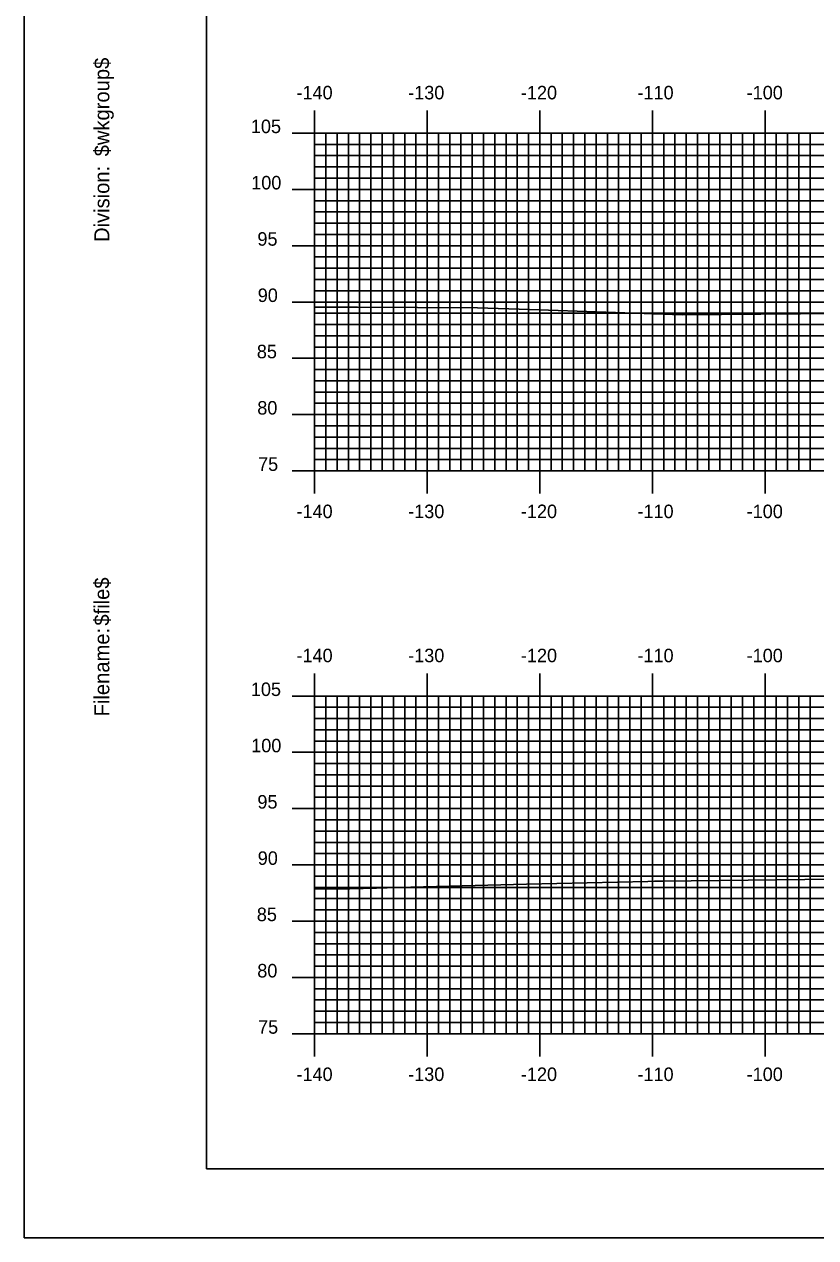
# Model space of a CAD drawing. Extents: x 854510 to 854853, y 364366 to 364586.
# Drawn here: x 854510 to 854580.2, y 364365.7 to 364473.5 of the extents above; entities that cross this region are included whole.
import ezdxf

# ---------------------------------------------------------------- set-up
doc = ezdxf.new("R2010")
doc.units = 0
for name, color, linetype in [('BORDER', 7, 'Continuous'), ('H_V ANNOTATION', 7, 'Continuous'), ('MAJOR', 7, 'Continuous'), ('MINOR', 7, 'Continuous'), ('PLOT BOUNDARY', 7, 'Continuous'), ('S_Roadway_Centerline', 7, 'Continuous')]:
    doc.layers.add(name, color=color, linetype=linetype)

msp = doc.modelspace()

# ---------------------------------------------------------------- linework, layer by layer
at = {"layer": 'BORDER'}
msp.add_lwpolyline([(854526.14, 364371.79), (854846.14, 364371.79), (854846.14, 364581.79), (854526.14, 364581.79)], close=True, dxfattribs=at)
at = {"layer": 'MAJOR'}
for p, q in [((854535.74, 364465.79), (854535.74, 364463.79)), ((854545.74, 364465.79), (854545.74, 364463.79)), ((854555.74, 364465.79), (854555.74, 364463.79)), ((854565.74, 364465.79), (854565.74, 364463.79)), ((854575.74, 364465.79), (854575.74, 364463.79)), ((854533.74, 364463.79), (854535.74, 364463.79)), ((854535.74, 364463.79), (854815.74, 364463.79)), ((854535.74, 364433.79), (854535.74, 364463.79)), ((854535.74, 364433.79), (854535.74, 364463.79)), ((854535.74, 364463.79), (854815.74, 364463.79)), ((854545.74, 364433.79), (854545.74, 364463.79)), ((854555.74, 364433.79), (854555.74, 364463.79)), ((854565.74, 364433.79), (854565.74, 364463.79)), ((854575.74, 364433.79), (854575.74, 364463.79)), ((854533.74, 364458.79), (854535.74, 364458.79)), ((854535.74, 364458.79), (854815.74, 364458.79)), ((854533.74, 364453.79), (854535.74, 364453.79)), ((854535.74, 364453.79), (854815.74, 364453.79)), ((854533.74, 364448.79), (854535.74, 364448.79)), ((854535.74, 364448.79), (854815.74, 364448.79)), ((854533.74, 364443.79), (854535.74, 364443.79)), ((854535.74, 364443.79), (854815.74, 364443.79)), ((854533.74, 364438.79), (854535.74, 364438.79)), ((854535.74, 364438.79), (854815.74, 364438.79)), ((854533.74, 364433.79), (854535.74, 364433.79)), ((854535.74, 364433.79), (854815.74, 364433.79)), ((854535.74, 364433.79), (854815.74, 364433.79)), ((854535.74, 364431.78), (854535.74, 364433.79)), ((854545.74, 364431.78), (854545.74, 364433.79)), ((854555.74, 364431.78), (854555.74, 364433.79)), ((854565.74, 364431.78), (854565.74, 364433.79)), ((854575.74, 364431.78), (854575.74, 364433.79)), ((854535.74, 364415.79), (854535.74, 364413.79)), ((854545.74, 364415.79), (854545.74, 364413.79)), ((854555.74, 364415.79), (854555.74, 364413.79)), ((854565.74, 364415.79), (854565.74, 364413.79)), ((854575.74, 364415.79), (854575.74, 364413.79)), ((854533.74, 364413.79), (854535.74, 364413.79)), ((854535.74, 364413.79), (854815.74, 364413.79)), ((854535.74, 364383.79), (854535.74, 364413.79)), ((854535.74, 364383.79), (854535.74, 364413.79)), ((854535.74, 364413.79), (854815.74, 364413.79)), ((854545.74, 364383.79), (854545.74, 364413.79)), ((854555.74, 364383.79), (854555.74, 364413.79)), ((854565.74, 364383.79), (854565.74, 364413.79)), ((854575.74, 364383.79), (854575.74, 364413.79)), ((854533.74, 364408.79), (854535.74, 364408.79)), ((854535.74, 364408.79), (854815.74, 364408.79)), ((854533.74, 364403.79), (854535.74, 364403.79)), ((854535.74, 364403.79), (854815.74, 364403.79)), ((854533.74, 364398.79), (854535.74, 364398.79)), ((854535.74, 364398.79), (854815.74, 364398.79)), ((854533.74, 364393.79), (854535.74, 364393.79)), ((854535.74, 364393.79), (854815.74, 364393.79)), ((854533.74, 364388.79), (854535.74, 364388.79)), ((854535.74, 364388.79), (854815.74, 364388.79)), ((854533.74, 364383.79), (854535.74, 364383.79)), ((854535.74, 364383.79), (854815.74, 364383.79)), ((854535.74, 364383.79), (854815.74, 364383.79)), ((854535.74, 364381.78), (854535.74, 364383.79)), ((854545.74, 364381.78), (854545.74, 364383.79)), ((854555.74, 364381.78), (854555.74, 364383.79)), ((854565.74, 364381.78), (854565.74, 364383.79)), ((854575.74, 364381.78), (854575.74, 364383.79))]:
    msp.add_line(p, q, dxfattribs=at)
at = {"layer": 'MINOR'}
for p, q in [((854536.74, 364433.79), (854536.74, 364463.79)), ((854537.74, 364433.79), (854537.74, 364463.79)), ((854538.74, 364433.79), (854538.74, 364463.79)), ((854539.74, 364433.79), (854539.74, 364463.79)), ((854540.74, 364433.79), (854540.74, 364463.79)), ((854541.74, 364433.79), (854541.74, 364463.79)), ((854542.74, 364433.79), (854542.74, 364463.79)), ((854543.74, 364433.79), (854543.74, 364463.79)), ((854544.74, 364433.79), (854544.74, 364463.79)), ((854546.74, 364433.79), (854546.74, 364463.79)), ((854547.74, 364433.79), (854547.74, 364463.79)), ((854548.74, 364433.79), (854548.74, 364463.79)), ((854549.74, 364433.79), (854549.74, 364463.79)), ((854550.74, 364433.79), (854550.74, 364463.79)), ((854551.74, 364433.79), (854551.74, 364463.79)), ((854552.74, 364433.79), (854552.74, 364463.79)), ((854553.74, 364433.79), (854553.74, 364463.79)), ((854554.74, 364433.79), (854554.74, 364463.79)), ((854556.74, 364433.79), (854556.74, 364463.79)), ((854557.74, 364433.79), (854557.74, 364463.79)), ((854558.74, 364433.79), (854558.74, 364463.79)), ((854559.74, 364433.79), (854559.74, 364463.79)), ((854560.74, 364433.79), (854560.74, 364463.79)), ((854561.74, 364433.79), (854561.74, 364463.79)), ((854562.74, 364433.79), (854562.74, 364463.79)), ((854563.74, 364433.79), (854563.74, 364463.79)), ((854564.74, 364433.79), (854564.74, 364463.79)), ((854566.74, 364433.79), (854566.74, 364463.79)), ((854567.74, 364433.79), (854567.74, 364463.79)), ((854568.74, 364433.79), (854568.74, 364463.79)), ((854569.74, 364433.79), (854569.74, 364463.79)), ((854570.74, 364433.79), (854570.74, 364463.79)), ((854571.74, 364433.79), (854571.74, 364463.79)), ((854572.74, 364433.79), (854572.74, 364463.79)), ((854573.74, 364433.79), (854573.74, 364463.79)), ((854574.74, 364433.79), (854574.74, 364463.79)), ((854576.74, 364433.79), (854576.74, 364463.79)), ((854577.74, 364433.79), (854577.74, 364463.79)), ((854578.74, 364433.79), (854578.74, 364463.79)), ((854579.74, 364433.79), (854579.74, 364463.79)), ((854535.74, 364462.79), (854815.74, 364462.79)), ((854535.74, 364462.79), (854537.75, 364462.79)), ((854535.74, 364461.79), (854815.74, 364461.79)), ((854535.74, 364461.79), (854537.75, 364461.79)), ((854535.74, 364460.79), (854815.74, 364460.79)), ((854535.74, 364460.79), (854537.75, 364460.79)), ((854535.74, 364459.79), (854815.74, 364459.79)), ((854535.74, 364459.79), (854537.75, 364459.79)), ((854535.74, 364457.79), (854815.74, 364457.79)), ((854535.74, 364457.79), (854537.75, 364457.79)), ((854535.74, 364456.79), (854815.74, 364456.79)), ((854535.74, 364456.79), (854537.75, 364456.79)), ((854535.74, 364455.79), (854815.74, 364455.79)), ((854535.74, 364455.79), (854537.75, 364455.79)), ((854535.74, 364454.79), (854815.74, 364454.79)), ((854535.74, 364454.79), (854537.75, 364454.79)), ((854535.74, 364452.79), (854815.74, 364452.79)), ((854535.74, 364452.79), (854537.75, 364452.79)), ((854535.74, 364451.79), (854815.74, 364451.79)), ((854535.74, 364451.79), (854537.75, 364451.79)), ((854535.74, 364450.79), (854815.74, 364450.79)), ((854535.74, 364450.79), (854537.75, 364450.79)), ((854535.74, 364449.79), (854815.74, 364449.79)), ((854535.74, 364449.79), (854537.75, 364449.79)), ((854535.74, 364447.79), (854815.74, 364447.79)), ((854535.74, 364447.79), (854537.75, 364447.79)), ((854535.74, 364446.79), (854815.74, 364446.79)), ((854535.74, 364446.79), (854537.75, 364446.79)), ((854535.74, 364445.79), (854815.74, 364445.79)), ((854535.74, 364445.79), (854537.75, 364445.79)), ((854535.74, 364444.79), (854815.74, 364444.79)), ((854535.74, 364444.79), (854537.75, 364444.79)), ((854535.74, 364442.79), (854815.74, 364442.79)), ((854535.74, 364442.79), (854537.75, 364442.79)), ((854535.74, 364441.79), (854815.74, 364441.79)), ((854535.74, 364441.79), (854537.75, 364441.79)), ((854535.74, 364440.79), (854815.74, 364440.79)), ((854535.74, 364440.79), (854537.75, 364440.79)), ((854535.74, 364439.79), (854815.74, 364439.79)), ((854535.74, 364439.79), (854537.75, 364439.79)), ((854535.74, 364437.79), (854815.74, 364437.79)), ((854535.74, 364437.79), (854537.75, 364437.79)), ((854535.74, 364436.79), (854815.74, 364436.79)), ((854535.74, 364436.79), (854537.75, 364436.79)), ((854535.74, 364435.79), (854815.74, 364435.79)), ((854535.74, 364435.79), (854537.75, 364435.79)), ((854535.74, 364434.79), (854815.74, 364434.79)), ((854535.74, 364434.79), (854537.75, 364434.79)), ((854536.74, 364383.79), (854536.74, 364413.79)), ((854537.74, 364383.79), (854537.74, 364413.79)), ((854538.74, 364383.79), (854538.74, 364413.79)), ((854539.74, 364383.79), (854539.74, 364413.79)), ((854540.74, 364383.79), (854540.74, 364413.79)), ((854541.74, 364383.79), (854541.74, 364413.79)), ((854542.74, 364383.79), (854542.74, 364413.79)), ((854543.74, 364383.79), (854543.74, 364413.79)), ((854544.74, 364383.79), (854544.74, 364413.79)), ((854546.74, 364383.79), (854546.74, 364413.79)), ((854547.74, 364383.79), (854547.74, 364413.79)), ((854548.74, 364383.79), (854548.74, 364413.79)), ((854549.74, 364383.79), (854549.74, 364413.79)), ((854550.74, 364383.79), (854550.74, 364413.79)), ((854551.74, 364383.79), (854551.74, 364413.79)), ((854552.74, 364383.79), (854552.74, 364413.79)), ((854553.74, 364383.79), (854553.74, 364413.79)), ((854554.74, 364383.79), (854554.74, 364413.79)), ((854556.74, 364383.79), (854556.74, 364413.79)), ((854557.74, 364383.79), (854557.74, 364413.79)), ((854558.74, 364383.79), (854558.74, 364413.79)), ((854559.74, 364383.79), (854559.74, 364413.79)), ((854560.74, 364383.79), (854560.74, 364413.79)), ((854561.74, 364383.79), (854561.74, 364413.79)), ((854562.74, 364383.79), (854562.74, 364413.79)), ((854563.74, 364383.79), (854563.74, 364413.79)), ((854564.74, 364383.79), (854564.74, 364413.79)), ((854566.74, 364383.79), (854566.74, 364413.79)), ((854567.74, 364383.79), (854567.74, 364413.79)), ((854568.74, 364383.79), (854568.74, 364413.79)), ((854569.74, 364383.79), (854569.74, 364413.79)), ((854570.74, 364383.79), (854570.74, 364413.79)), ((854571.74, 364383.79), (854571.74, 364413.79)), ((854572.74, 364383.79), (854572.74, 364413.79)), ((854573.74, 364383.79), (854573.74, 364413.79)), ((854574.74, 364383.79), (854574.74, 364413.79)), ((854576.74, 364383.79), (854576.74, 364413.79)), ((854577.74, 364383.79), (854577.74, 364413.79)), ((854578.74, 364383.79), (854578.74, 364413.79)), ((854579.74, 364383.79), (854579.74, 364413.79)), ((854535.74, 364412.79), (854815.74, 364412.79)), ((854535.74, 364412.79), (854537.75, 364412.79)), ((854535.74, 364411.79), (854815.74, 364411.79)), ((854535.74, 364411.79), (854537.75, 364411.79)), ((854535.74, 364410.79), (854815.74, 364410.79)), ((854535.74, 364410.79), (854537.75, 364410.79)), ((854535.74, 364409.79), (854815.74, 364409.79)), ((854535.74, 364409.79), (854537.75, 364409.79)), ((854535.74, 364407.79), (854815.74, 364407.79)), ((854535.74, 364407.79), (854537.75, 364407.79)), ((854535.74, 364406.79), (854815.74, 364406.79)), ((854535.74, 364406.79), (854537.75, 364406.79)), ((854535.74, 364405.79), (854815.74, 364405.79)), ((854535.74, 364405.79), (854537.75, 364405.79)), ((854535.74, 364404.79), (854815.74, 364404.79)), ((854535.74, 364404.79), (854537.75, 364404.79)), ((854535.74, 364402.79), (854815.74, 364402.79)), ((854535.74, 364402.79), (854537.75, 364402.79)), ((854535.74, 364401.79), (854815.74, 364401.79)), ((854535.74, 364401.79), (854537.75, 364401.79)), ((854535.74, 364400.79), (854815.74, 364400.79)), ((854535.74, 364400.79), (854537.75, 364400.79)), ((854535.74, 364399.79), (854815.74, 364399.79)), ((854535.74, 364399.79), (854537.75, 364399.79)), ((854535.74, 364397.79), (854815.74, 364397.79)), ((854535.74, 364397.79), (854537.75, 364397.79)), ((854535.74, 364396.79), (854815.74, 364396.79)), ((854535.74, 364396.79), (854537.75, 364396.79)), ((854535.74, 364395.79), (854815.74, 364395.79)), ((854535.74, 364395.79), (854537.75, 364395.79)), ((854535.74, 364394.79), (854815.74, 364394.79)), ((854535.74, 364394.79), (854537.75, 364394.79)), ((854535.74, 364392.79), (854815.74, 364392.79)), ((854535.74, 364392.79), (854537.75, 364392.79)), ((854535.74, 364391.79), (854815.74, 364391.79)), ((854535.74, 364391.79), (854537.75, 364391.79)), ((854535.74, 364390.79), (854815.74, 364390.79)), ((854535.74, 364390.79), (854537.75, 364390.79)), ((854535.74, 364389.79), (854815.74, 364389.79)), ((854535.74, 364389.79), (854537.75, 364389.79)), ((854535.74, 364387.79), (854815.74, 364387.79)), ((854535.74, 364387.79), (854537.75, 364387.79)), ((854535.74, 364386.79), (854815.74, 364386.79)), ((854535.74, 364386.79), (854537.75, 364386.79)), ((854535.74, 364385.79), (854815.74, 364385.79)), ((854535.74, 364385.79), (854537.75, 364385.79)), ((854535.74, 364384.79), (854815.74, 364384.79)), ((854535.74, 364384.79), (854537.75, 364384.79))]:
    msp.add_line(p, q, dxfattribs=at)
at = {"layer": 'PLOT BOUNDARY'}
msp.add_lwpolyline([(854509.96, 364365.67), (854849.96, 364365.67), (854849.96, 364585.67), (854509.96, 364585.67)], close=True, dxfattribs=at)
at = {"layer": 'S_Roadway_Centerline'}
for points in [[(854535.74, 364448.34), (854539.56, 364448.34), (854550.22, 364448.27), (854554.82, 364448.12), (854568.37, 364447.66), (854585.89, 364447.79), (854586.57, 364447.8), (854587.15, 364447.81), (854600.18, 364448.06), (854606.34, 364448.19), (854612.32, 364448.2), (854623.42, 364447.86), (854624.15, 364447.85), (854635.84, 364447.92), (854643.39, 364448.07), (854657.11, 364448)], [(854535.74, 364396.63), (854538.88, 364396.67), (854541.23, 364396.71), (854543.13, 364396.78), (854554.57, 364397.09), (854565.33, 364397.32), (854565.94, 364397.33), (854566.66, 364397.34), (854584.35, 364397.55), (854594.24, 364397.5), (854600.17, 364397.36), (854605.32, 364397.46), (854612.64, 364397.54), (854621.71, 364397.82), (854624.26, 364397.84), (854626.35, 364397.81), (854636.42, 364397.33), (854647.19, 364397.3), (854648.75, 364397.28), (854668.36, 364396.97)]]:
    msp.add_lwpolyline(points, dxfattribs=at)

# ---------------------------------------------------------------- texts
at = {"layer": 'BORDER'}
for s, p in [('$wkgroup$', (854517.51, 364461.73)), ('Division:', (854517.51, 364454.12)), ('$file$', (854517.51, 364420.04)), ('Filename:', (854517.51, 364411.98))]:
    msp.add_text(s, height=1.339, rotation=90, dxfattribs=at).set_placement(p)
at = {"layer": 'H_V ANNOTATION'}
for s, p in [('-140', (854534.13, 364466.79)), ('-130', (854544.05, 364466.79)), ('-120', (854554.06, 364466.79)), ('-110', (854564.41, 364466.79)), ('-100', (854574.11, 364466.79)), ('105', (854530.08, 364463.79)), ('100', (854530.11, 364458.79)), ('95', (854530.66, 364453.79)), ('90', (854530.69, 364448.79)), ('85', (854530.61, 364443.79)), ('80', (854530.65, 364438.79)), ('75', (854530.72, 364433.79)), ('-140', (854534.13, 364429.59)), ('-130', (854544.05, 364429.59)), ('-120', (854554.06, 364429.59)), ('-110', (854564.41, 364429.59)), ('-100', (854574.11, 364429.59)), ('-140', (854534.13, 364416.79)), ('-130', (854544.05, 364416.79)), ('-120', (854554.06, 364416.79)), ('-110', (854564.41, 364416.79)), ('-100', (854574.11, 364416.79)), ('105', (854530.08, 364413.79)), ('100', (854530.11, 364408.79)), ('95', (854530.66, 364403.79)), ('90', (854530.69, 364398.79)), ('85', (854530.61, 364393.79)), ('80', (854530.65, 364388.79)), ('75', (854530.72, 364383.79)), ('-140', (854534.13, 364379.59)), ('-130', (854544.05, 364379.59)), ('-120', (854554.06, 364379.59)), ('-110', (854564.41, 364379.59)), ('-100', (854574.11, 364379.59))]:
    msp.add_text(s, height=1.2, dxfattribs=at).set_placement(p)
at = {"layer": 'MAJOR'}
for p in [(854535.73, 364433.79), (854535.73, 364383.79)]:
    msp.add_text('-', height=0.012, dxfattribs=at).set_placement(p)

doc.saveas('drawing.dxf')
